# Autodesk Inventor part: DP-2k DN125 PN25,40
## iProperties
Created: 2009-08
Part Number: DP-2k DN125 PN25,40
Document SubType Name: Modelowanie
Designer: Marcin Pyzik
Author: Marcin Pyzik
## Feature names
1. Wyciągnięcie proste1 [Extrusion]
2. Faza1 [Chamfer]
3. Bryła wyprowadzona1 [Tagging]
